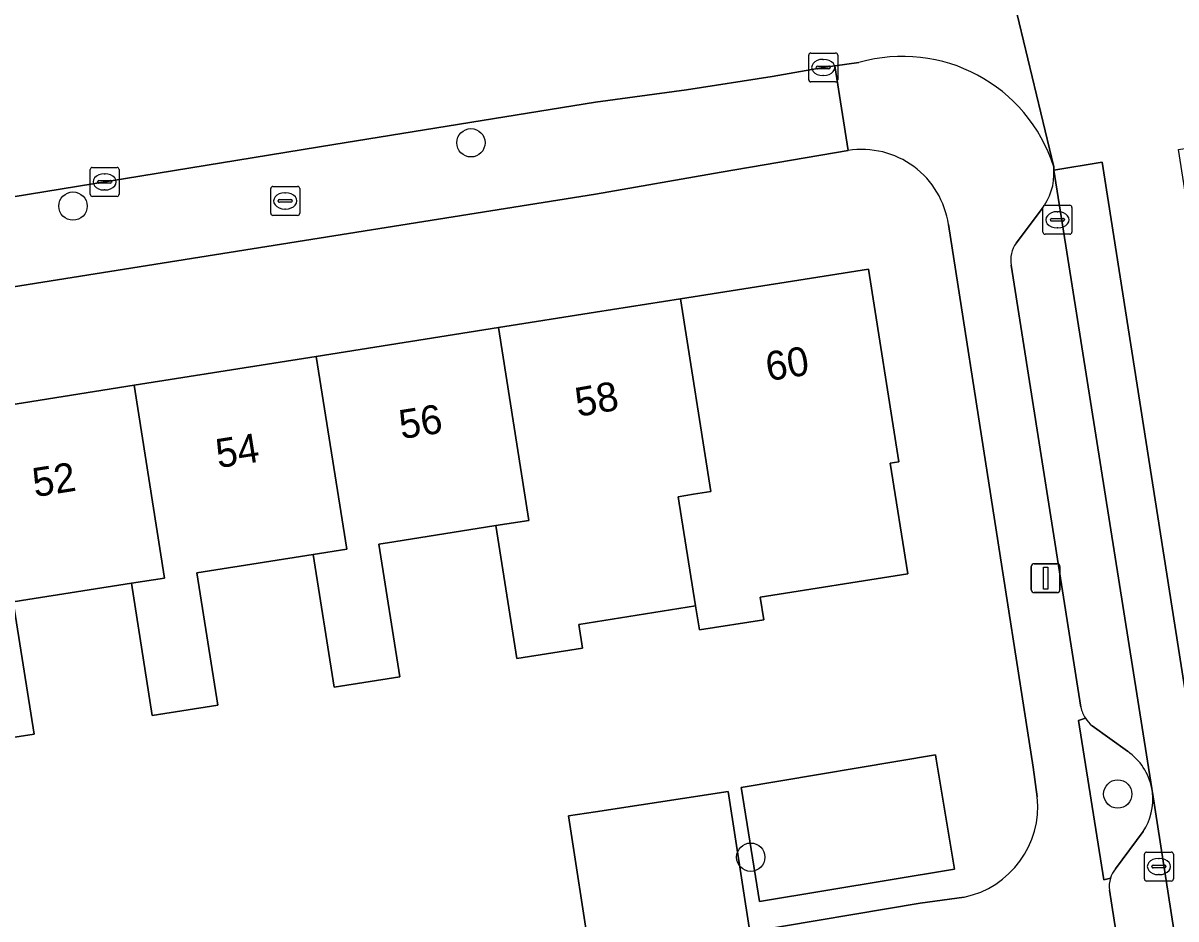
# Model space of a CAD drawing. Extents: x 160077 to 160948, y 386481 to 387498.
# Drawn here: x 160480.23 to 160520.05, y 387428.44 to 387459.37 of the extents above; entities that cross this region are included whole.
import ezdxf

# ---------------------------------------------------------------- set-up
doc = ezdxf.new("R2010")
doc.units = 0
for name, color, linetype in [('IMGEO_Boom', 7, 'Continuous'), ('IMGEO_Brandkraan', 7, 'Continuous'), ('IMGEO_Erf', 7, 'Continuous'), ('IMGEO_Groenvoorziening', 7, 'Continuous'), ('IMGEO_Kolk', 7, 'Continuous'), ('IMGEO_Lichtmast', 7, 'Continuous'), ('IMGEO_Pand', 7, 'Continuous'), ('IMGEO_Pand_nummerreeks', 7, 'Continuous'), ('IMGEO_Parkeervlak_open', 7, 'Continuous'), ('IMGEO_Rijbaan_lokaal_gesloten', 7, 'Continuous'), ('IMGEO_Rijbaan_lokaal_open', 7, 'Continuous'), ('IMGEO_Voetpad_open', 7, 'Continuous')]:
    doc.layers.add(name, color=color, linetype=linetype)

msp = doc.modelspace()

# ---------------------------------------------------------------- linework, layer by layer
at = {"layer": 'IMGEO_Boom'}
for centre in [(160495.699, 387455.234), (160481.953, 387453.049), (160518.042, 387432.751), (160505.365, 387430.571)]:
    msp.add_circle(centre, 0.489, dxfattribs=at)
at = {"layer": 'IMGEO_Brandkraan'}
for p, q in [((160488.858, 387453.728), (160489.71, 387453.728)), ((160488.783, 387452.802), (160488.783, 387453.654)), ((160489.271, 387453.508), (160489.296, 387453.508)), ((160489.784, 387453.654), (160489.784, 387452.802)), ((160489.042, 387453.222), (160489.042, 387453.234)), ((160489.48, 387453.185), (160489.082, 387453.185)), ((160489.085, 387453.271), (160489.483, 387453.271)), ((160489.294, 387452.948), (160489.269, 387452.948)), ((160489.526, 387453.234), (160489.526, 387453.222)), ((160489.71, 387452.728), (160488.858, 387452.728))]:
    msp.add_line(p, q, dxfattribs=at)
for points in [[(160488.858, 387453.728), (160489.71, 387453.728)], [(160488.783, 387452.802), (160488.783, 387453.654)], [(160489.784, 387453.654), (160489.784, 387452.802)], [(160489.71, 387452.728), (160488.858, 387452.728)]]:
    msp.add_lwpolyline(points, dxfattribs=at)
for centre, radius, start, end in [((160488.86, 387453.652), 0.0765, 91.552, 178.448), ((160488.86, 387453.652), 0.0765, 91.552, 178.448), ((160489.708, 387453.652), 0.0765, 1.552, 88.448), ((160489.708, 387453.652), 0.0765, 1.552, 88.448), ((160489.082, 387453.231), 0.0403, 85.8775, 175.7526), ((160489.079, 387453.221), 0.0366, 178.938, 274.7102), ((160489.483, 387453.228), 0.043, 264.8664, 352.4533), ((160489.487, 387453.233), 0.0386, 1.7309, 96.639), ((160488.86, 387452.804), 0.0765, 181.552, 268.448), ((160488.86, 387452.804), 0.0765, 181.552, 268.448), ((160489.708, 387452.804), 0.0765, 271.552, 358.448), ((160489.708, 387452.804), 0.0765, 271.552, 358.448)]:
    msp.add_arc(centre, radius, start, end, dxfattribs=at)
for centre, major_axis, ratio, start_param, end_param in [((160489.27, 387453.228), (-0.387, 0.002), 0.722429, 4.712389, 7.853982), ((160489.295, 387453.228), (-0.39, 0.002), 0.717154, 1.570796, 4.712389)]:
    msp.add_ellipse(centre, major_axis=major_axis, ratio=ratio, start_param=start_param, end_param=end_param, dxfattribs=at)
at = {"layer": 'IMGEO_Erf'}
for points in [[(160508.733, 387454.967), (160504.347, 387454.224), (160500, 387453.464), (160440.626, 387444.012)], [(160515.262, 387432.65), (160515.116, 387433.681), (160512.191, 387452.41)], [(160477.778, 387445.867), (160484.067, 387446.862), (160490.357, 387447.857), (160496.647, 387448.852), (160500, 387449.382), (160502.937, 387449.847), (160509.427, 387450.873), (160510.479, 387444.222), (160510.184, 387444.175), (160510.787, 387440.355), (160505.691, 387439.552), (160505.816, 387438.768), (160503.59, 387438.42), (160503.459, 387439.245), (160499.424, 387438.608), (160499.553, 387437.788), (160497.287, 387437.433), (160496.561, 387442.021), (160493.031, 387441.462), (160492.519, 387441.381), (160493.244, 387436.8), (160490.974, 387436.445), (160490.249, 387441.023), (160486.665, 387440.455), (160486.228, 387440.386), (160486.952, 387435.816), (160484.692, 387435.462), (160483.969, 387440.029), (160480.396, 387439.464), (160479.887, 387439.384), (160480.61, 387434.823), (160478.361, 387434.471)], [(160437.638, 387439.901), (160440.28, 387423.011), (160466.781, 387427.157), (160466.438, 387429.462), (160468.933, 387429.847), (160469.275, 387427.547), (160474.262, 387428.327), (160475.073, 387423.208), (160499.818, 387427.147), (160499.065, 387431.995), (160500, 387432.139), (160504.58, 387432.844), (160505.333, 387427.999), (160511.22, 387428.987), (160512.734, 387429.19)]]:
    msp.add_lwpolyline(points, dxfattribs=at)
msp.add_lwpolyline([(160511.74, 387434.1), (160511.765, 387433.951), (160512.397, 387430.16), (160505.668, 387429.038), (160505.04, 387432.915), (160505.029, 387432.981)], close=True, dxfattribs=at)
for centre, radius, start, end in [((160509.203, 387451.986), 3.018, 8.0789, 98.9593), ((160512.078, 387432.323), 3.201, 281.8262, 5.8674)]:
    msp.add_arc(centre, radius, start, end, dxfattribs=at)
at = {"layer": 'IMGEO_Groenvoorziening'}
for points in [[(160516.924, 387435.369), (160516.683, 387435.291), (160517.564, 387429.789), (160517.786, 387429.844)], [(160518.382, 387434.226), (160517.156, 387435.104)], [(160519.237, 387432.804), (160519.215, 387432.944)], [(160517.961, 387430.167), (160518.922, 387431.456)]]:
    msp.add_lwpolyline(points, dxfattribs=at)
msp.add_lwpolyline([(160504.58, 387432.844), (160500, 387432.139), (160499.065, 387431.995), (160499.818, 387427.147), (160500, 387427.176), (160505.333, 387427.999)], close=True, dxfattribs=at)
for centre, radius, start, end in [((160517.924, 387436.011), 1.188, 212.6777, 229.7247), ((160517.227, 387432.564), 2.024, 10.8233, 55.2056), ((160517.223, 387432.564), 2.028, 326.8927, 6.8017), ((160518.665, 387429.577), 0.918, 140.0136, 163.0891)]:
    msp.add_arc(centre, radius, start, end, dxfattribs=at)
at = {"layer": 'IMGEO_Kolk'}
for p, q in [((160507.367, 387457.408), (160507.367, 387458.26)), ((160507.442, 387458.334), (160508.294, 387458.334)), ((160507.855, 387458.114), (160507.88, 387458.114)), ((160508.368, 387458.26), (160508.368, 387457.408)), ((160507.626, 387457.828), (160507.626, 387457.84)), ((160508.064, 387457.791), (160507.666, 387457.791)), ((160507.669, 387457.877), (160508.067, 387457.877)), ((160508.11, 387457.84), (160508.11, 387457.828)), ((160508.294, 387457.334), (160507.442, 387457.334)), ((160507.878, 387457.554), (160507.853, 387457.554)), ((160482.546, 387453.459), (160482.546, 387454.311)), ((160482.621, 387454.385), (160483.473, 387454.385)), ((160483.034, 387454.165), (160483.059, 387454.165)), ((160483.547, 387454.311), (160483.547, 387453.459)), ((160482.805, 387453.879), (160482.805, 387453.891)), ((160483.243, 387453.842), (160482.845, 387453.842)), ((160482.848, 387453.928), (160483.246, 387453.928)), ((160483.289, 387453.891), (160483.289, 387453.879)), ((160483.473, 387453.385), (160482.621, 387453.385)), ((160483.057, 387453.605), (160483.032, 387453.605)), ((160515.457, 387452.15), (160515.457, 387453.002)), ((160515.532, 387453.076), (160516.384, 387453.076)), ((160516.458, 387453.002), (160516.458, 387452.15)), ((160515.716, 387452.57), (160515.716, 387452.582)), ((160516.154, 387452.533), (160515.756, 387452.533)), ((160515.759, 387452.619), (160516.157, 387452.619)), ((160515.945, 387452.856), (160515.97, 387452.856)), ((160516.2, 387452.582), (160516.2, 387452.57)), ((160515.968, 387452.296), (160515.943, 387452.296)), ((160516.384, 387452.076), (160515.532, 387452.076)), ((160518.962, 387429.822), (160518.962, 387430.674)), ((160519.037, 387430.748), (160519.889, 387430.748)), ((160519.963, 387430.674), (160519.963, 387429.822)), ((160519.221, 387430.242), (160519.221, 387430.254)), ((160519.659, 387430.205), (160519.261, 387430.205)), ((160519.264, 387430.291), (160519.662, 387430.291)), ((160519.45, 387430.528), (160519.475, 387430.528)), ((160519.705, 387430.254), (160519.705, 387430.242)), ((160519.473, 387429.968), (160519.448, 387429.968)), ((160519.889, 387429.748), (160519.037, 387429.748))]:
    msp.add_line(p, q, dxfattribs=at)
for points in [[(160507.367, 387457.408), (160507.367, 387458.26)], [(160507.442, 387458.334), (160508.294, 387458.334)], [(160508.368, 387458.26), (160508.368, 387457.408)], [(160508.294, 387457.334), (160507.442, 387457.334)], [(160482.546, 387453.459), (160482.546, 387454.311)], [(160482.621, 387454.385), (160483.473, 387454.385)], [(160483.547, 387454.311), (160483.547, 387453.459)], [(160483.473, 387453.385), (160482.621, 387453.385)], [(160515.457, 387452.15), (160515.457, 387453.002)], [(160515.532, 387453.076), (160516.384, 387453.076)], [(160516.458, 387453.002), (160516.458, 387452.15)], [(160516.384, 387452.076), (160515.532, 387452.076)], [(160518.962, 387429.822), (160518.962, 387430.674)], [(160519.037, 387430.748), (160519.889, 387430.748)], [(160519.963, 387430.674), (160519.963, 387429.822)], [(160519.889, 387429.748), (160519.037, 387429.748)]]:
    msp.add_lwpolyline(points, dxfattribs=at)
for centre, radius, start, end in [((160507.444, 387458.258), 0.0765, 91.552, 178.448), ((160507.444, 387458.258), 0.0765, 91.552, 178.448), ((160508.292, 387458.258), 0.0765, 1.552, 88.448), ((160508.292, 387458.258), 0.0765, 1.552, 88.448), ((160507.666, 387457.837), 0.0403, 85.8775, 175.7526), ((160507.663, 387457.827), 0.0366, 178.938, 274.7102), ((160508.067, 387457.834), 0.043, 264.8664, 352.4533), ((160508.071, 387457.839), 0.0386, 1.7309, 96.639), ((160507.444, 387457.41), 0.0765, 181.552, 268.448), ((160507.444, 387457.41), 0.0765, 181.552, 268.448), ((160508.292, 387457.41), 0.0765, 271.552, 358.448), ((160508.292, 387457.41), 0.0765, 271.552, 358.448), ((160482.623, 387454.309), 0.0765, 91.552, 178.448), ((160482.623, 387454.309), 0.0765, 91.552, 178.448), ((160483.471, 387454.309), 0.0765, 1.552, 88.448), ((160483.471, 387454.309), 0.0765, 1.552, 88.448), ((160482.845, 387453.888), 0.0403, 85.8775, 175.7526), ((160482.842, 387453.878), 0.0366, 178.938, 274.7102), ((160483.246, 387453.885), 0.043, 264.8664, 352.4533), ((160483.25, 387453.89), 0.0386, 1.7309, 96.639), ((160482.623, 387453.461), 0.0765, 181.552, 268.448), ((160482.623, 387453.461), 0.0765, 181.552, 268.448), ((160483.471, 387453.461), 0.0765, 271.552, 358.448), ((160483.471, 387453.461), 0.0765, 271.552, 358.448), ((160515.534, 387453), 0.0765, 91.552, 178.448), ((160515.534, 387453), 0.0765, 91.552, 178.448), ((160516.382, 387453), 0.0765, 1.552, 88.448), ((160516.382, 387453), 0.0765, 1.552, 88.448), ((160515.756, 387452.579), 0.0403, 85.8775, 175.7526), ((160515.753, 387452.569), 0.0366, 178.938, 274.7102), ((160516.157, 387452.576), 0.043, 264.8664, 352.4533), ((160516.161, 387452.581), 0.0386, 1.7309, 96.639), ((160515.534, 387452.152), 0.0765, 181.552, 268.448), ((160515.534, 387452.152), 0.0765, 181.552, 268.448), ((160516.382, 387452.152), 0.0765, 271.552, 358.448), ((160516.382, 387452.152), 0.0765, 271.552, 358.448), ((160519.039, 387430.672), 0.0765, 91.552, 178.448), ((160519.039, 387430.672), 0.0765, 91.552, 178.448), ((160519.887, 387430.672), 0.0765, 1.552, 88.448), ((160519.887, 387430.672), 0.0765, 1.552, 88.448), ((160519.261, 387430.251), 0.0403, 85.8775, 175.7526), ((160519.258, 387430.241), 0.0366, 178.938, 274.7102), ((160519.662, 387430.248), 0.043, 264.8664, 352.4533), ((160519.666, 387430.253), 0.0386, 1.7309, 96.639), ((160519.039, 387429.824), 0.0765, 181.552, 268.448), ((160519.039, 387429.824), 0.0765, 181.552, 268.448), ((160519.887, 387429.824), 0.0765, 271.552, 358.448), ((160519.887, 387429.824), 0.0765, 271.552, 358.448)]:
    msp.add_arc(centre, radius, start, end, dxfattribs=at)
for centre, major_axis, ratio, start_param, end_param in [((160507.854, 387457.834), (-0.387, 0.002), 0.722429, 4.712389, 7.853982), ((160507.879, 387457.834), (-0.39, 0.002), 0.717154, 1.570796, 4.712389), ((160483.033, 387453.885), (-0.387, 0.002), 0.722429, 4.712389, 7.853982), ((160483.058, 387453.885), (-0.39, 0.002), 0.717154, 1.570796, 4.712389), ((160515.944, 387452.576), (-0.387, 0.002), 0.722429, 4.712389, 7.853982), ((160515.969, 387452.576), (-0.39, 0.002), 0.717154, 1.570796, 4.712389), ((160519.449, 387430.248), (-0.387, 0.002), 0.722429, 4.712389, 7.853982), ((160519.474, 387430.248), (-0.39, 0.002), 0.717154, 1.570796, 4.712389)]:
    msp.add_ellipse(centre, major_axis=major_axis, ratio=ratio, start_param=start_param, end_param=end_param, dxfattribs=at)
at = {"layer": 'IMGEO_Lichtmast'}
for p, q in [((160515.055, 387439.804), (160515.055, 387440.604)), ((160515.055, 387440.604), (160515.055, 387439.804)), ((160515.155, 387440.704), (160515.945, 387440.704)), ((160515.945, 387440.704), (160515.155, 387440.704)), ((160516.045, 387440.604), (160516.045, 387439.804)), ((160516.045, 387439.804), (160516.045, 387440.604)), ((160515.945, 387439.704), (160515.155, 387439.704)), ((160515.155, 387439.704), (160515.945, 387439.704))]:
    msp.add_line(p, q, dxfattribs=at)
msp.add_lwpolyline([(160515.475, 387440.579), (160515.625, 387440.579), (160515.625, 387439.829), (160515.475, 387439.829), (160515.475, 387440.579)], dxfattribs=at)
for centre, start, end in [((160515.155, 387440.604), 90, 180), ((160515.155, 387440.604), 90, 180), ((160515.945, 387440.604), 0, 90), ((160515.945, 387440.604), 360, 90), ((160515.155, 387439.804), 180, 270), ((160515.155, 387439.804), 180, 270), ((160515.945, 387439.804), 270, 0), ((160515.945, 387439.804), 270, 0)]:
    msp.add_arc(centre, 0.1, start, end, dxfattribs=at)
at = {"layer": 'IMGEO_Pand'}
for points in [[(160509.427, 387450.873), (160502.937, 387449.847), (160503.989, 387443.194), (160503.392, 387443.1), (160502.862, 387443.016), (160503.459, 387439.245), (160503.59, 387438.42), (160505.816, 387438.768), (160505.691, 387439.552), (160510.787, 387440.355), (160510.184, 387444.175), (160510.479, 387444.222)], [(160502.937, 387449.847), (160500, 387449.382), (160496.647, 387448.852), (160497.699, 387442.2), (160496.561, 387442.021), (160497.287, 387437.433), (160499.553, 387437.788), (160499.424, 387438.608), (160503.459, 387439.245), (160502.862, 387443.016), (160503.392, 387443.1), (160503.989, 387443.194)], [(160496.647, 387448.852), (160490.357, 387447.857), (160491.409, 387441.205), (160490.249, 387441.023), (160490.974, 387436.445), (160493.244, 387436.8), (160492.519, 387441.381), (160493.031, 387441.462), (160496.561, 387442.021), (160497.699, 387442.2)], [(160490.357, 387447.857), (160484.067, 387446.862), (160485.119, 387440.209), (160483.969, 387440.029), (160484.692, 387435.462), (160486.952, 387435.816), (160486.228, 387440.386), (160486.665, 387440.455), (160490.249, 387441.023), (160491.409, 387441.205)], [(160484.067, 387446.862), (160477.778, 387445.867), (160478.83, 387439.216), (160477.639, 387439.028), (160478.361, 387434.471), (160480.61, 387434.823), (160479.887, 387439.384), (160480.396, 387439.464), (160483.969, 387440.029), (160485.119, 387440.209)], [(160511.74, 387434.1), (160505.029, 387432.981), (160505.04, 387432.915), (160505.668, 387429.038), (160512.397, 387430.16), (160511.765, 387433.951)]]:
    msp.add_lwpolyline(points, close=True, dxfattribs=at)
at = {"layer": 'IMGEO_Parkeervlak_open'}
for points in [[(160519.215, 387432.944), (160515.838, 387454.295)], [(160515.411, 387452.93), (160514.529, 387451.769)], [(160514.362, 387451.011), (160516.764, 387435.752)], [(160517.156, 387435.104), (160518.382, 387434.226)], [(160523.536, 387405.179), (160519.237, 387432.804)], [(160518.922, 387431.456), (160517.961, 387430.167)], [(160517.757, 387429.437), (160521.087, 387408.071)]]:
    msp.add_lwpolyline(points, dxfattribs=at)
for centre, radius, start, end in [((160513.784, 387454.188), 2.056, 322.2784, 2.9801), ((160515.321, 387451.197), 0.977, 144.1625, 190.9881), ((160517.928, 387436.013), 1.193, 192.654, 212.6919), ((160517.924, 387436.011), 1.188, 212.6777, 229.7247), ((160517.227, 387432.564), 2.024, 10.8233, 55.2056), ((160517.223, 387432.564), 2.028, 326.8927, 6.8017), ((160518.681, 387429.576), 0.934, 163.3099, 188.5389), ((160518.665, 387429.577), 0.918, 140.0136, 163.0891)]:
    msp.add_arc(centre, radius, start, end, dxfattribs=at)
at = {"layer": 'IMGEO_Rijbaan_lokaal_gesloten'}
msp.add_lwpolyline([(160515.838, 387454.295), (160519.215, 387432.944), (160519.237, 387432.804), (160523.536, 387405.179), (160523.542, 387405.144), (160525.127, 387395.067), (160526.805, 387395.323), (160517.498, 387454.571)], close=True, dxfattribs=at)
at = {"layer": 'IMGEO_Rijbaan_lokaal_open'}
for points in [[(160511.877, 387470.779), (160511.946, 387470.578), (160515.829, 387454.409), (160515.838, 387454.295), (160517.498, 387454.571), (160526.805, 387395.323), (160529.432, 387395.722), (160520.138, 387455.008), (160521.823, 387455.263), (160520.873, 387461.374), (160520.495, 387464.396), (160520.467, 387464.488), (160520.443, 387467.682), (160520.455, 387469.472)], [(160515.829, 387454.409), (160511.946, 387470.578), (160511.957, 387470.345)], [(160490.962, 387455.175), (160500, 387456.638), (160503.147, 387457.064), (160506.105, 387457.527), (160507.868, 387457.834), (160508.269, 387457.889), (160509.101, 387458.002)], [(160438.905, 387446.811), (160468.797, 387451.566), (160490.962, 387455.175)]]:
    msp.add_lwpolyline(points, dxfattribs=at)
msp.add_arc((160510.618, 387452.746), 5.47, 17.6966, 106.0957, dxfattribs=at)
at = {"layer": 'IMGEO_Voetpad_open'}
for points in [[(160508.733, 387454.967), (160508.269, 387457.889), (160507.868, 387457.834), (160506.105, 387457.527), (160503.147, 387457.064), (160500, 387456.638), (160490.962, 387455.175), (160468.797, 387451.566), (160438.905, 387446.811)], [(160509.101, 387458.002), (160508.269, 387457.889), (160508.733, 387454.967)], [(160440.626, 387444.012), (160500, 387453.464), (160504.347, 387454.224), (160508.733, 387454.967)], [(160515.838, 387454.295), (160515.829, 387454.409)], [(160514.529, 387451.769), (160515.411, 387452.93)], [(160512.191, 387452.41), (160515.116, 387433.681), (160515.262, 387432.65)], [(160516.764, 387435.752), (160514.362, 387451.011)], [(160517.786, 387429.844), (160517.564, 387429.789), (160516.683, 387435.291), (160516.924, 387435.369)], [(160521.087, 387408.071), (160517.757, 387429.437)], [(160512.734, 387429.19), (160511.22, 387428.987), (160505.333, 387427.999), (160500, 387427.176), (160499.818, 387427.147), (160475.073, 387423.208)]]:
    msp.add_lwpolyline(points, dxfattribs=at)
for centre, radius, start, end in [((160510.618, 387452.746), 5.47, 17.6966, 106.0957), ((160509.203, 387451.986), 3.018, 8.0789, 98.9593), ((160513.784, 387454.188), 2.056, 322.2784, 2.9801), ((160515.321, 387451.197), 0.977, 144.1625, 190.9881), ((160517.928, 387436.013), 1.193, 192.654, 212.6919), ((160512.078, 387432.323), 3.201, 281.8262, 5.8674), ((160518.681, 387429.576), 0.934, 163.3099, 188.5389)]:
    msp.add_arc(centre, radius, start, end, dxfattribs=at)

# ---------------------------------------------------------------- texts
at = {"layer": 'IMGEO_Pand_nummerreeks'}
for s, rotation, p in [('60', 8.9897, (160505.961, 387447.004)), ('58', 10.0096, (160499.391, 387445.77)), ('56', 8.9897, (160493.298, 387445.001)), ('54', 8.9897, (160486.968, 387444)), ('52', 8.9897, (160480.636, 387442.998))]:
    msp.add_text(s, height=1, rotation=rotation, dxfattribs=at).set_placement(p)

doc.saveas('drawing.dxf')
